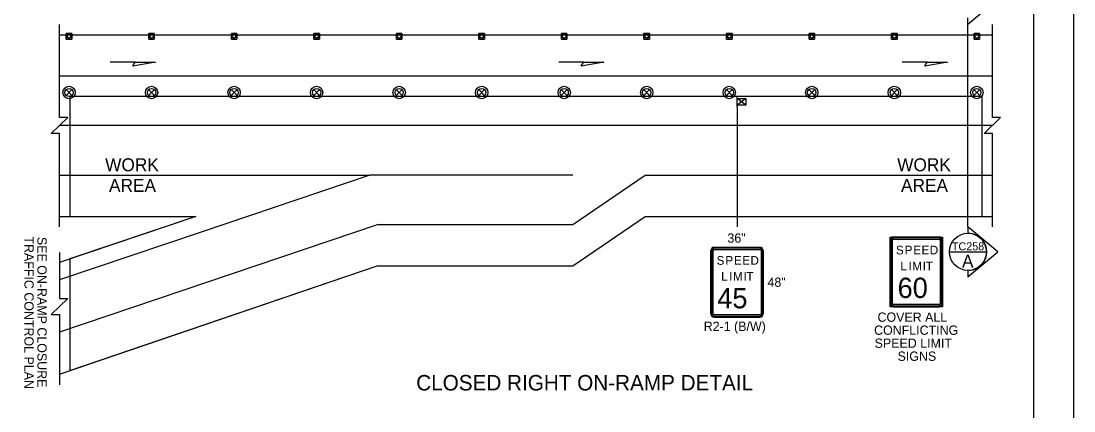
# Model space of a CAD drawing. Extents: x 99999 to 100116, y 99995 to 100013.
# Drawn here: x 100047.9 to 100056.06, y 100001.64 to 100004.66 of the extents above; entities that cross this region are included whole.
import ezdxf

# ---------------------------------------------------------------- set-up
doc = ezdxf.new("R2010")
doc.units = 0
for name, color, linetype in [('Default', 7, 'Continuous'), ('RD_MK_LineEdgeYellow', 7, 'Continuous'), ('RD_MK_LineLane', 7, 'Continuous'), ('SH_DE_DetailHeading2Text', 7, 'Continuous'), ('SH_GI_PlotLimits', 7, 'Continuous'), ('SH_GI_SectionCut', 7, 'Continuous'), ('SH_GI_SheetBorder', 7, 'Continuous'), ('TR_SN_ConstructionSigns', 7, 'Continuous'), ('TR_WZ_PortableSignMount5ftMinBlk-Wht', 7, 'Continuous'), ('TR_WZ_TrafficCone', 7, 'Continuous'), ('TR_WZ_TrafficSafetyDrum', 7, 'Continuous'), ('TR_WZ_WorkAreaLabel', 7, 'Continuous'), ('TR_WZ_WorkZoneDetails', 7, 'Continuous')]:
    doc.layers.add(name, color=color, linetype=linetype)

msp = doc.modelspace()

# ---------------------------------------------------------------- linework, layer by layer
at = {"layer": 'RD_MK_LineEdgeYellow'}
for p, q in [((100048.195, 100004.238), (100055.43, 100004.238)), ((100048.195, 100003.47), (100049.2533, 100003.47)), ((100052.1758, 100003.086), (100052.7368, 100003.47)), ((100052.7368, 100003.47), (100055.43, 100003.47)), ((100050.6655, 100003.086), (100048.195, 100002.2517)), ((100050.6655, 100003.086), (100052.1758, 100003.086)), ((100049.2943, 100003.0282), (100048.195, 100002.657))]:
    msp.add_line(p, q, dxfattribs=at)
at = {"layer": 'RD_MK_LineLane'}
for points in [[(100055.43, 100003.854), (100048.195, 100003.854)], [(100052.1758, 100003.47), (100050.6024, 100003.47)]]:
    msp.add_lwpolyline(points, dxfattribs=at)
at = {"layer": 'SH_GI_PlotLimits'}
msp.add_lwpolyline([(100039.0625, 99999.6875), (100056.0625, 99999.6875), (100056.0625, 100010.6875), (100039.0625, 100010.6875)], close=True, dxfattribs=at)
at = {"layer": 'SH_GI_SectionCut'}
for p, q in [((100055.4733, 100004.8328), (100055.2407, 100004.638)), ((100055.2407, 100004.638), (100055.2407, 100004.6888)), ((100055.2407, 100003.0699), (100055.2407, 100004.638)), ((100055.2407, 100003.07), (100055.2407, 100003.0191)), ((100055.4733, 100002.8751), (100055.2407, 100003.07)), ((100055.2407, 100002.6802), (100055.4733, 100002.8751)), ((100055.2407, 100002.7311), (100055.2407, 100002.6802))]:
    msp.add_line(p, q, dxfattribs=at)
msp.add_lwpolyline([(100055.0967, 100002.8751), (100055.3847, 100002.8751)], dxfattribs=at)
msp.add_circle((100055.2407, 100002.8751), 0.144, dxfattribs=at)
msp.add_arc((100055.2407, 100002.8751), 0.144, 269.99779, 90.00221, dxfattribs=at)
at = {"layer": 'SH_GI_SheetBorder'}
msp.add_line((100055.75, 100010.375), (100055.75, 100000), dxfattribs=at)
at = {"layer": 'TR_SN_ConstructionSigns'}
for p, q in [((100054.638, 100002.4753), (100054.638, 100002.9646)), ((100054.638, 100002.9646), (100054.638, 100002.4753)), ((100054.6451, 100002.9646), (100054.6451, 100002.4753)), ((100054.6549, 100002.4753), (100054.6549, 100002.9646)), ((100054.6633, 100002.99), (100055.0177, 100002.99)), ((100055.0177, 100002.99), (100054.6633, 100002.99)), ((100055.0177, 100002.9829), (100054.6633, 100002.9829)), ((100054.6633, 100002.9731), (100055.0177, 100002.9731)), ((100055.0261, 100002.9646), (100055.0261, 100002.4753)), ((100055.036, 100002.4753), (100055.036, 100002.9646)), ((100055.043, 100002.9646), (100055.043, 100002.4753)), ((100055.043, 100002.4753), (100055.043, 100002.9646)), ((100053.2475, 100002.3953), (100053.2475, 100002.8846)), ((100053.2475, 100002.8846), (100053.2475, 100002.3953)), ((100053.2546, 100002.8846), (100053.2546, 100002.3953)), ((100053.2644, 100002.3953), (100053.2644, 100002.8846)), ((100053.2728, 100002.91), (100053.6272, 100002.91)), ((100053.6272, 100002.91), (100053.2728, 100002.91)), ((100053.6272, 100002.9029), (100053.2728, 100002.9029)), ((100053.2728, 100002.8931), (100053.6272, 100002.8931)), ((100053.6357, 100002.8846), (100053.6357, 100002.3953)), ((100053.6455, 100002.3953), (100053.6455, 100002.8846)), ((100053.6525, 100002.8846), (100053.6525, 100002.3953)), ((100053.6525, 100002.3953), (100053.6525, 100002.8846)), ((100055.0177, 100002.4668), (100054.6633, 100002.4668)), ((100053.6272, 100002.3868), (100053.2728, 100002.3868)), ((100053.2728, 100002.377), (100053.6272, 100002.377)), ((100054.6633, 100002.457), (100055.0177, 100002.457)), ((100055.0177, 100002.45), (100054.6633, 100002.45)), ((100054.6633, 100002.45), (100055.0177, 100002.45)), ((100053.6272, 100002.37), (100053.2728, 100002.37)), ((100053.2728, 100002.37), (100053.6272, 100002.37))]:
    msp.add_line(p, q, dxfattribs=at)
msp.add_lwpolyline([(100054.638, 100002.99), (100055.043, 100002.99), (100055.043, 100002.45), (100054.638, 100002.45)], close=True, dxfattribs=at)
for centre, radius, start, end in [((100054.6633, 100002.9646), 0.0253, 90, 180), ((100054.6633, 100002.9646), 0.0253, 90, 180), ((100054.6633, 100002.9646), 0.0183, 90, 180), ((100054.6633, 100002.9646), 0.00844, 90, 180), ((100055.0177, 100002.9646), 0.0253, 0, 90), ((100055.0177, 100002.9646), 0.0253, 360, 90), ((100055.0177, 100002.9646), 0.0183, 0, 90), ((100055.0177, 100002.9646), 0.00844, 360, 90), ((100053.2728, 100002.8846), 0.0253, 90, 180), ((100053.2728, 100002.8846), 0.0253, 90, 180), ((100053.2728, 100002.8846), 0.0183, 90, 180), ((100053.2728, 100002.8846), 0.00844, 90, 180), ((100053.6272, 100002.8846), 0.0253, 360, 90), ((100053.6272, 100002.8846), 0.0253, 360, 90), ((100053.6272, 100002.8846), 0.0183, 0, 90), ((100053.6272, 100002.8846), 0.00844, 360, 90), ((100054.6633, 100002.4753), 0.0253, 180, 270), ((100054.6633, 100002.4753), 0.0253, 180, 270), ((100054.6633, 100002.4753), 0.0183, 180, 270), ((100054.6633, 100002.4753), 0.00844, 180, 270), ((100055.0177, 100002.4753), 0.0253, 270, 0), ((100055.0177, 100002.4753), 0.0183, 270, 360), ((100055.0177, 100002.4753), 0.00844, 270, 0), ((100055.0177, 100002.4753), 0.0253, 270, 0), ((100053.2728, 100002.3953), 0.0253, 180, 270), ((100053.2728, 100002.3953), 0.0253, 180, 270), ((100053.2728, 100002.3953), 0.0183, 180, 270), ((100053.2728, 100002.3953), 0.00844, 180, 270), ((100053.6272, 100002.3953), 0.0253, 270, 360), ((100053.6272, 100002.3953), 0.0183, 270, 360), ((100053.6272, 100002.3953), 0.00844, 270, 0), ((100053.6272, 100002.3953), 0.0253, 270, 360)]:
    msp.add_arc(centre, radius, start, end, dxfattribs=at)
at = {"layer": 'TR_WZ_PortableSignMount5ftMinBlk-Wht'}
for p, q in [((100053.45, 100003.998), (100053.45, 100004.078)), ((100053.5167, 100004.064), (100053.45, 100004.012)), ((100053.5167, 100004.012), (100053.45, 100004.064)), ((100053.4834, 100004.038), (100053.4834, 100004.038)), ((100053.4835, 100004.038), (100053.4835, 100004.038))]:
    msp.add_line(p, q, dxfattribs=at)
msp.add_lwpolyline([(100053.5167, 100004.064), (100053.5167, 100004.012), (100053.45, 100004.012), (100053.45, 100004.064)], close=True, dxfattribs=at)
at = {"layer": 'TR_WZ_TrafficCone'}
for points in [[(100048.2481, 100004.566), (100048.2907, 100004.566), (100048.2907, 100004.5233), (100048.2481, 100004.5233), (100048.2481, 100004.566)], [(100048.2481, 100004.5233), (100048.2907, 100004.5233), (100048.2907, 100004.566), (100048.2481, 100004.566), (100048.2481, 100004.5233)], [(100048.8881, 100004.566), (100048.9307, 100004.566), (100048.9307, 100004.5233), (100048.8881, 100004.5233), (100048.8881, 100004.566)], [(100048.8881, 100004.5233), (100048.9307, 100004.5233), (100048.9307, 100004.566), (100048.8881, 100004.566), (100048.8881, 100004.5233)], [(100049.5281, 100004.566), (100049.5707, 100004.566), (100049.5707, 100004.5233), (100049.5281, 100004.5233), (100049.5281, 100004.566)], [(100049.5281, 100004.5233), (100049.5707, 100004.5233), (100049.5707, 100004.566), (100049.5281, 100004.566), (100049.5281, 100004.5233)], [(100050.1681, 100004.566), (100050.2107, 100004.566), (100050.2107, 100004.5233), (100050.1681, 100004.5233), (100050.1681, 100004.566)], [(100050.1681, 100004.5233), (100050.2107, 100004.5233), (100050.2107, 100004.566), (100050.1681, 100004.566), (100050.1681, 100004.5233)], [(100050.8081, 100004.566), (100050.8507, 100004.566), (100050.8507, 100004.5233), (100050.8081, 100004.5233), (100050.8081, 100004.566)], [(100050.8081, 100004.5233), (100050.8507, 100004.5233), (100050.8507, 100004.566), (100050.8081, 100004.566), (100050.8081, 100004.5233)], [(100051.4481, 100004.566), (100051.4907, 100004.566), (100051.4907, 100004.5233), (100051.4481, 100004.5233), (100051.4481, 100004.566)], [(100051.4481, 100004.5233), (100051.4907, 100004.5233), (100051.4907, 100004.566), (100051.4481, 100004.566), (100051.4481, 100004.5233)], [(100052.0881, 100004.566), (100052.1307, 100004.566), (100052.1307, 100004.5233), (100052.0881, 100004.5233), (100052.0881, 100004.566)], [(100052.0881, 100004.5233), (100052.1307, 100004.5233), (100052.1307, 100004.566), (100052.0881, 100004.566), (100052.0881, 100004.5233)], [(100052.7281, 100004.566), (100052.7707, 100004.566), (100052.7707, 100004.5233), (100052.7281, 100004.5233), (100052.7281, 100004.566)], [(100052.7281, 100004.5233), (100052.7707, 100004.5233), (100052.7707, 100004.566), (100052.7281, 100004.566), (100052.7281, 100004.5233)], [(100053.3681, 100004.566), (100053.4107, 100004.566), (100053.4107, 100004.5233), (100053.3681, 100004.5233), (100053.3681, 100004.566)], [(100053.3681, 100004.5233), (100053.4107, 100004.5233), (100053.4107, 100004.566), (100053.3681, 100004.566), (100053.3681, 100004.5233)], [(100054.0081, 100004.566), (100054.0507, 100004.566), (100054.0507, 100004.5233), (100054.0081, 100004.5233), (100054.0081, 100004.566)], [(100054.0081, 100004.5233), (100054.0507, 100004.5233), (100054.0507, 100004.566), (100054.0081, 100004.566), (100054.0081, 100004.5233)], [(100054.6481, 100004.566), (100054.6907, 100004.566), (100054.6907, 100004.5233), (100054.6481, 100004.5233), (100054.6481, 100004.566)], [(100054.6481, 100004.5233), (100054.6907, 100004.5233), (100054.6907, 100004.566), (100054.6481, 100004.566), (100054.6481, 100004.5233)], [(100055.2881, 100004.566), (100055.3307, 100004.566), (100055.3307, 100004.5233), (100055.2881, 100004.5233), (100055.2881, 100004.566)], [(100055.2881, 100004.5233), (100055.3307, 100004.5233), (100055.3307, 100004.566), (100055.2881, 100004.566), (100055.2881, 100004.5233)]]:
    msp.add_lwpolyline(points, dxfattribs=at)
for centre in [(100048.2694, 100004.5446), (100048.9094, 100004.5446), (100049.5494, 100004.5446), (100050.1894, 100004.5446), (100050.8294, 100004.5446), (100051.4694, 100004.5446), (100052.1094, 100004.5446), (100052.7494, 100004.5446), (100053.3894, 100004.5446), (100054.0294, 100004.5446), (100054.6694, 100004.5446), (100055.3094, 100004.5446)]:
    msp.add_circle(centre, 0.0133, dxfattribs=at)
at = {"layer": 'TR_WZ_TrafficSafetyDrum'}
for p, q in [((100048.2468, 100004.1326), (100048.292, 100004.0873)), ((100048.292, 100004.1326), (100048.2468, 100004.0873)), ((100048.8868, 100004.1326), (100048.932, 100004.0873)), ((100048.932, 100004.1326), (100048.8868, 100004.0873)), ((100049.5268, 100004.1326), (100049.572, 100004.0873)), ((100049.572, 100004.1326), (100049.5268, 100004.0873)), ((100050.1668, 100004.1326), (100050.212, 100004.0873)), ((100050.212, 100004.1326), (100050.1668, 100004.0873)), ((100050.8068, 100004.1326), (100050.852, 100004.0873)), ((100050.852, 100004.1326), (100050.8068, 100004.0873)), ((100051.4468, 100004.1326), (100051.492, 100004.0873)), ((100051.492, 100004.1326), (100051.4468, 100004.0873)), ((100052.0868, 100004.1326), (100052.132, 100004.0873)), ((100052.132, 100004.1326), (100052.0868, 100004.0873)), ((100052.7268, 100004.1326), (100052.772, 100004.0873)), ((100052.772, 100004.1326), (100052.7268, 100004.0873)), ((100053.3668, 100004.1326), (100053.412, 100004.0873)), ((100053.412, 100004.1326), (100053.3668, 100004.0873)), ((100054.0068, 100004.1326), (100054.052, 100004.0873)), ((100054.052, 100004.1326), (100054.0068, 100004.0873)), ((100054.6468, 100004.1326), (100054.692, 100004.0873)), ((100054.692, 100004.1326), (100054.6468, 100004.0873)), ((100055.2868, 100004.1326), (100055.332, 100004.0873)), ((100055.332, 100004.1326), (100055.2868, 100004.0873))]:
    msp.add_line(p, q, dxfattribs=at)
for centre, radius in [((100048.2694, 100004.11), 0.048), ((100048.2694, 100004.11), 0.048), ((100048.2694, 100004.11), 0.032), ((100048.9094, 100004.11), 0.048), ((100048.9094, 100004.11), 0.048), ((100048.9094, 100004.11), 0.032), ((100049.5494, 100004.11), 0.048), ((100049.5494, 100004.11), 0.048), ((100049.5494, 100004.11), 0.032), ((100050.1894, 100004.11), 0.048), ((100050.1894, 100004.11), 0.048), ((100050.1894, 100004.11), 0.032), ((100050.8294, 100004.11), 0.048), ((100050.8294, 100004.11), 0.048), ((100050.8294, 100004.11), 0.032), ((100051.4694, 100004.11), 0.048), ((100051.4694, 100004.11), 0.048), ((100051.4694, 100004.11), 0.032), ((100052.1094, 100004.11), 0.048), ((100052.1094, 100004.11), 0.048), ((100052.1094, 100004.11), 0.032), ((100052.7494, 100004.11), 0.048), ((100052.7494, 100004.11), 0.048), ((100052.7494, 100004.11), 0.032), ((100053.3894, 100004.11), 0.048), ((100053.3894, 100004.11), 0.048), ((100053.3894, 100004.11), 0.032), ((100054.0294, 100004.11), 0.048), ((100054.0294, 100004.11), 0.048), ((100054.0294, 100004.11), 0.032), ((100054.6694, 100004.11), 0.048), ((100054.6694, 100004.11), 0.048), ((100054.6694, 100004.11), 0.032), ((100055.3094, 100004.11), 0.048), ((100055.3094, 100004.11), 0.048), ((100055.3094, 100004.11), 0.032)]:
    msp.add_circle(centre, radius, dxfattribs=at)
at = {"layer": 'TR_WZ_WorkZoneDetails'}
for p, q in [((100048.195, 100004.558), (100055.43, 100004.558)), ((100048.782, 100004.344), (100048.5891, 100004.344)), ((100052.2594, 100004.344), (100052.0665, 100004.344)), ((100054.9242, 100004.344), (100054.7313, 100004.344)), ((100053.45, 100003.998), (100053.45, 100003.07)), ((100049.2533, 100003.47), (100050.6024, 100003.47)), ((100050.6024, 100003.47), (100049.2943, 100003.0282)), ((100048.195, 100003.15), (100049.2533, 100003.15)), ((100049.2533, 100003.15), (100048.195, 100002.7929)), ((100052.1758, 100002.766), (100052.7368, 100003.15)), ((100052.7368, 100003.15), (100055.43, 100003.15)), ((100048.195, 100001.928), (100050.6601, 100002.766)), ((100050.6601, 100002.766), (100052.1758, 100002.766))]:
    msp.add_line(p, q, dxfattribs=at)
for points in [[(100048.195, 100003.07), (100048.195, 100003.792), (100048.131, 100003.792), (100048.259, 100003.9159), (100048.195, 100003.9159), (100048.195, 100004.638)], [(100055.43, 100003.07), (100055.43, 100003.792), (100055.366, 100003.792), (100055.494, 100003.9159), (100055.43, 100003.9159), (100055.43, 100004.638)], [(100048.195, 100002.8701), (100048.195, 100002.5136), (100048.259, 100002.5136), (100048.131, 100002.3897), (100048.195, 100002.3897), (100048.195, 100001.8453)]]:
    msp.add_lwpolyline(points, dxfattribs=at)
for points in [[(100048.9392, 100004.344), (100048.7641, 100004.3132), (100048.782, 100004.344)], [(100052.4166, 100004.344), (100052.2415, 100004.3132), (100052.2594, 100004.344)], [(100055.0815, 100004.344), (100054.9064, 100004.3132), (100054.9242, 100004.344)], [(100048.275, 100004.078), (100048.275, 100003.15), (100049.2533, 100003.15), (100048.275, 100002.8199), (100048.275, 100002.8199), (100048.275, 100002.8199), (100048.275, 100001.9552), (100048.275, 100001.9552), (100048.275, 100001.9552), (100049.3215, 100002.3109), (100050.6601, 100002.766), (100052.1758, 100002.766), (100052.7368, 100003.15), (100055.35, 100003.15), (100055.35, 100004.078)]]:
    msp.add_lwpolyline(points, close=True, dxfattribs=at)

# ---------------------------------------------------------------- texts
at = {"layer": 'Default'}
for s, height, p in [('S', 0.0675, (100053.2914, 100002.775)), ('P', 0.0675, (100053.3596, 100002.775)), ('E', 0.0675, (100053.4257, 100002.775)), ('E', 0.0675, (100053.4899, 100002.775)), ('D', 0.0675, (100053.554, 100002.775)), ('L', 0.0675, (100053.3265, 100002.6512)), ('I', 0.0675, (100053.3886, 100002.6512)), ('M', 0.0675, (100053.4183, 100002.6512)), ('I', 0.0675, (100053.4993, 100002.6512)), ('T', 0.0675, (100053.5229, 100002.6512)), ('45', 0.1575, (100053.2965, 100002.4375))]:
    msp.add_text(s, height=height, dxfattribs=at).set_placement(p)
at = {"layer": 'SH_DE_DetailHeading2Text'}
msp.add_text('CLOSED RIGHT ON-RAMP DETAIL', height=0.12, rotation=360, dxfattribs=at).set_placement((100050.9618, 100001.8009))
at = {"layer": 'SH_GI_SectionCut'}
msp.add_text('TC258', height=0.0625, dxfattribs=at).set_placement((100055.1158, 100002.8867))
msp.add_text('A', height=0.1, rotation=359.99005, dxfattribs=at).set_placement((100055.1945, 100002.7531))
at = {"layer": 'TR_SN_ConstructionSigns'}
for s, height, p in [('36"', 0.072, (100053.3753, 100002.946)), ('S', 0.0675, (100054.6819, 100002.855)), ('P', 0.0675, (100054.7501, 100002.855)), ('E', 0.0675, (100054.8162, 100002.855)), ('E', 0.0675, (100054.8803, 100002.855)), ('D', 0.0675, (100054.9445, 100002.855)), ('L', 0.0675, (100054.717, 100002.7312)), ('I', 0.0675, (100054.7791, 100002.7312)), ('M', 0.0675, (100054.8088, 100002.7312)), ('I', 0.0675, (100054.8898, 100002.7312)), ('T', 0.0675, (100054.9134, 100002.7312)), ('60', 0.1575, (100054.6949, 100002.5175)), ('COVER ALL', 0.072, (100054.5392, 100002.333)), ('CONFLICTING', 0.072, (100054.5128, 100002.2322)), ('SPEED LIMIT', 0.072, (100054.5168, 100002.1314)), ('SIGNS', 0.072, (100054.6947, 100002.0306))]:
    msp.add_text(s, height=height, dxfattribs=at).set_placement(p)
at = {"layer": 'TR_WZ_WorkAreaLabel'}
for s, p in [('WORK', (100048.5496, 100003.5)), ('WORK', (100054.6919, 100003.5)), ('AREA', (100048.5793, 100003.34)), ('AREA', (100054.7215, 100003.34))]:
    msp.add_text(s, height=0.1, dxfattribs=at).set_placement(p)
at = {"layer": 'TR_WZ_WorkZoneDetails'}
for s, p in [('TRAFFIC CONTROL PLAN', (100047.923, 100002.9948)), ('SEE ON-RAMP CLOSURE', (100048.0238, 100002.9908))]:
    msp.add_text(s, height=0.072, rotation=270, dxfattribs=at).set_placement(p)
for s, p in [('48"', (100053.6858, 100002.604)), ('R2-1 (B/W)', (100053.1913, 100002.262))]:
    msp.add_text(s, height=0.072, dxfattribs=at).set_placement(p)

doc.saveas('drawing.dxf')
